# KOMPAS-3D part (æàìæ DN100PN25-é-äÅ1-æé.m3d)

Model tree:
1. Объединить компоненты:1  (labels: СЕНС DN100PN25-В-ДП1)
2. Эскиз:1
3. Операция выдавливания:1
     Расстояние 1 = 14
4. Фаска:1
     Угол = 45; Длина 1 = 2; Длина 2 = 2

Referenced files in D:\Савин\!СЕНСОР\3D для заказчика\!Новый перечень\СЕНС\5. СЕНС-В-ДП\DN100\: СЕНС DN100PN25-В-ДП1.a3d
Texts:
  СЕНС DN100PN25-В-ДП1-СВ
  ООО НПП Сенсор
  СЕНС DN100PN25-В-ДП1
